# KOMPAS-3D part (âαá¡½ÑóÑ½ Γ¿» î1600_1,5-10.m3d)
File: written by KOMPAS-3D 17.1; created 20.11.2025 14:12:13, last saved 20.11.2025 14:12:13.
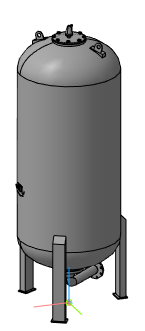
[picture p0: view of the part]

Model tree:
1. Операция без истории:2

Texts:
  REVIT MATERIAL OVERRIDDEN
  REVIT MATERIAL ID
  REVIT SUBCATEGORY ID
  REVIT CATEGORY ID
  REVIT ELEMENT ID
  REVIT BREP TAG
